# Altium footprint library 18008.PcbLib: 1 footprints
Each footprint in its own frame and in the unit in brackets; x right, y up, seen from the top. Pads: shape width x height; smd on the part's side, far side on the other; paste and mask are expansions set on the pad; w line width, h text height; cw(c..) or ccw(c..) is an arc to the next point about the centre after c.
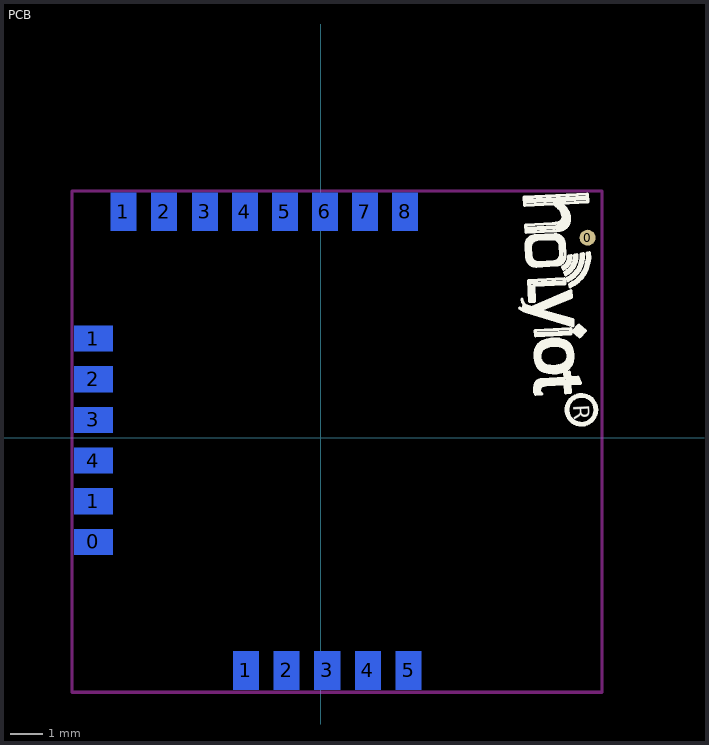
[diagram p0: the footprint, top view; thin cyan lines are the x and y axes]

## PCB [mm]
pads (20):
  rect 1.2x0.8 smd far side: 0(-7.092,-3.249) 1(-7.092,3.101) 1(-7.092,-1.979) 2(-7.092,1.831) 3(-7.092,0.561) 4(-7.092,-0.709)
  round 0.5 smd: 0(8.338,6.251)
  rect 0.8x1.2 smd far side: 1(-6.152,7.061) 1(-2.332,-7.259) 2(-4.882,7.061) 2(-1.062,-7.259) 3(-3.612,7.061) 3(0.208,-7.259) 4(-2.362,7.061) 4(1.478,-7.259) 5(-1.112,7.061) 5(2.748,-7.259) 6(0.138,7.061) 7(1.388,7.061) 8(2.638,7.061)
Top Overlay:
  circle w0.15: c8.147,0.878 r0.45
  region: 6.704,1.663 6.718,1.384 6.878,1.392 6.863,1.672
  region: 7.657,2.014 7.686,1.445 7.786,1.45 7.757,2.019
  region: 6.727,1.785 6.735,1.645 8.073,1.715 8.066,1.855
  region: 6.973,2.087 7.08,2.206 6.879,2.387 6.772,2.268
  region: 6.769,2.831 6.888,2.724 7.068,2.924 6.949,3.031
  region: 7.551,2.252 7.67,2.145 7.85,2.345 7.732,2.452
  region: 7.685,2.743 7.792,2.862 7.592,3.043 7.485,2.924
  region: 6.882,3.035 6.892,2.845 7.561,2.88 7.551,3.07
  region: 6.72,2.886 6.753,2.247 6.913,2.255 6.88,2.894
  region: 6.915,2.215 6.924,2.045 7.673,2.085 7.664,2.254
  region: 7.701,2.887 7.735,2.238 7.865,2.245 7.831,2.894
  region: 7.911,3.355 8.075,3.207 8.215,3.363 8.052,3.511
  region: 6.748,3.308 6.752,3.228 7.78,3.282 7.776,3.362
  region: 7.825,3.51 7.881,3.691 6.305,4.173 6.25,3.991
  region: 7.851,4.406 7.772,4.593 6.506,4.056 6.586,3.869
  region: 6.55,4.79 6.575,4.3 6.645,4.304 6.62,4.793
  region: 6.545,4.88 6.55,4.79 7.578,4.844 7.574,4.933
  region: 6.551,5.541 6.557,5.421 6.667,5.427 6.66,5.546
  region: 6.516,6.21 6.521,6.1 6.641,6.106 6.635,6.216
  region: 7.429,5.597 7.437,5.437 7.557,5.443 7.549,5.603
  region: 7.374,6.255 7.38,6.145 7.55,6.154 7.544,6.264
  region: 6.575,5.462 6.579,5.382 7.468,5.429 7.464,5.508
  region: 7.479,6.17 7.513,5.511 7.593,5.515 7.559,6.174
  region: 6.457,6.187 6.496,5.438 6.586,5.442 6.547,6.191
  region: 6.492,6.269 6.497,6.189 7.525,6.243 7.521,6.323
  region: 7.542,6.476 7.79,6.805 7.594,6.954 7.345,6.624
  region: 6.455,6.607 6.462,6.457 7.641,6.519 7.633,6.669
  region: 7.265,7.391 7.673,6.761 7.816,6.854 7.407,7.483
  region: 6.409,7.476 6.417,7.316 8.295,7.415 8.286,7.574
  lines w0.1: 6.211,4.06 ccw(c6.661,4.63) 6.447,3.936 7.886,3.491 7.875,3.697 6.867,3.977 6.865,4.001 7.833,4.383 7.822,4.605 6.594,4.073 6.454,4.112 cw(c6.514,4.324) 6.294,4.336 ; 6.735,5.363 cw(c6.721,5.643) 6.441,5.628 6.421,6.016 cw(c6.7,6.031) 6.686,6.31 7.315,6.343 cw(c7.33,6.064) 7.609,6.078 7.63,5.691 cw(c7.35,5.676) 7.365,5.396 6.735,5.363 ; 7.034,1.652 7.642,1.684 7.657,1.408 7.805,1.415 7.791,1.686 8.118,1.703 8.036,1.892 7.781,1.878 7.772,2.052 7.623,2.045 7.633,1.87 6.907,1.82 ccw(c6.928,1.523) 6.825,1.803 ccw(c6.894,1.615) 6.698,1.657 cw(c6.366,1.729) 6.694,1.638 ccw(c7.103,1.526) 6.713,1.358 6.911,1.369 cw(c6.998,1.527) 6.867,1.402 cw(c6.94,1.471) 6.84,1.462 cw(c7.067,1.484) 6.856,1.571 cw(c6.949,1.532) 6.912,1.626 cw(c7.058,1.253) 7.034,1.652 ; 7.498,7.114 ccw(c6.825,6.581) 7.272,7.314 6.376,7.267 6.363,7.514 8.329,7.617 8.342,7.37 7.488,7.325 cw(c7.006,6.647) 7.733,7.051 cw(c7.246,6.845) 7.77,6.777 cw(c7.433,6.821) 7.478,6.484 cw(c7.117,9.195) 7.26,6.463 6.42,6.419 6.408,6.647 7.248,6.691 ccw(c7.204,7.525) 7.443,6.725 ccw(c7.391,6.897) 7.571,6.909 ccw(c7.176,6.884) 7.498,7.114 ; 7.593,3.044 ccw(c7.306,2.23) 6.934,3.008 ccw(c7.107,2.647) 6.72,2.75 ccw(c7.414,2.566) 6.743,2.311 ccw(c7.117,2.453) 6.983,2.076 ccw(c7.272,2.889) 7.642,2.11 ccw(c7.47,2.471) 7.857,2.369 ccw(c7.164,2.553) 7.834,2.808 ccw(c7.46,2.666) 7.594,3.043 ; 7.798,4.722 7.772,4.791 ccw(c7.366,5.668) 8.327,5.773 8.4,5.784 cw(c7.366,5.668) 7.798,4.722 ; 6.5,4.92 7.617,4.978 7.626,4.813 6.655,4.762 6.681,4.267 6.535,4.26 6.5,4.92 ; 6.557,5.961 cw(c6.776,5.972) 6.765,6.192 7.249,6.217 cw(c7.261,5.997) 7.481,6.009 7.495,5.736 cw(c7.275,5.724) 7.287,5.504 6.802,5.479 cw(c6.791,5.699) 6.571,5.687 6.557,5.961 ; 6.706,3.351 7.814,3.409 7.822,3.246 6.714,3.188 6.706,3.351 ; 6.883,2.701 cw(c7.116,2.587) 7.015,2.826 cw(c7.313,2.121) 7.53,2.855 cw(c7.456,2.606) 7.674,2.748 cw(c7.394,2.565) 7.692,2.412 cw(c7.46,2.531) 7.56,2.291 cw(c7.267,2.999) 7.045,2.266 cw(c7.12,2.514) 6.9,2.376 cw(c7.184,2.554) 6.883,2.701 ; 7.563,5.336 ccw(c7.366,5.668) 7.752,5.683 7.826,5.695 cw(c7.366,5.668) 7.59,5.266 7.563,5.336 ; 7.628,5.166 ccw(c7.366,5.668) 7.931,5.711 8.004,5.723 cw(c7.366,5.668) 7.655,5.096 7.628,5.166 ; 7.7,4.978 ccw(c7.366,5.668) 8.129,5.742 8.202,5.753 cw(c7.366,5.668) 7.727,4.909 7.7,4.978 ; 7.895,3.33 8.07,3.525 8.265,3.349 8.09,3.155 7.895,3.33
  text "R" at 7.889,1.015 h0.5
Bottom Overlay:
  text "P0.12" at -3.862,-3.489 h0.5
  text "P0.11" at -4.052,-2.169 h0.5
  text "VDD" at -4.668,5.951 h0.5
  text "GND" at -5.922,5.951 h0.5
  text "P0.25" at 2.858,5.951 h0.5
  text "HOLYIOT-18008" at 6.608,-5.099 h0.9
  text "NFC2" at -4.152,-0.939 h0.5
  text "NFC1" at -4.319,0.344 h0.5
  text "SWD" at 3.048,-4.919 h0.5
  text "P0.26" at 1.604,5.951 h0.5
  text "P0.28" at -0.905,5.951 h0.5
  text "BATT" at -4.152,1.628 h0.5
  text "P0.27" at 0.349,5.951 h0.5
  text "GND" at -4.652,2.911 h0.5
  text "P0.30" at -3.413,5.951 h0.5
  text "P0.29" at -2.159,5.951 h0.5
  text "CLK" at 1.773,-4.919 h0.5
  text "RST" at 0.498,-4.919 h0.5
  text "VDD" at -2.052,-4.919 h0.5
  text "GND" at -0.777,-4.919 h0.5
Keep-Out Layer:
  lines w0.1: -7.762,-7.939 8.788,-7.939 8.788,7.711 -7.762,7.711 -7.762,-7.939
